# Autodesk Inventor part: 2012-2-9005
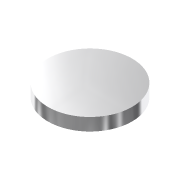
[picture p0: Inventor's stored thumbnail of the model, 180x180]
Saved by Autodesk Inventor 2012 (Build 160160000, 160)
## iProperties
Created: 2011-12
Part Number: 2012-2-9005
Material: Stainless Steel
Document SubType Name: Modeling
Designer: Admin
Density: 8.08 g/cm^3
Mass: 0.951903 g
Surface Area: 2.04204 cm^2
Volume: 0.11781 cm^3
Description: Wear Plate
Author: Admin
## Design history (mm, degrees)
sketch "Sketch1"
  geometry: C1 r 5 at (0, 0); 1 further point
  constraints: 1 centre point, 1 coincident
  dimensions: "d0" = 10 dimension on point (0, 0) C1.centre C1; "d0" = 10 diameter of C1
extrude "Extrusion1" new body sketch "Sketch1" distance "d1" = 1.5; taper "d2" = 0 deg
body "Solid1"
